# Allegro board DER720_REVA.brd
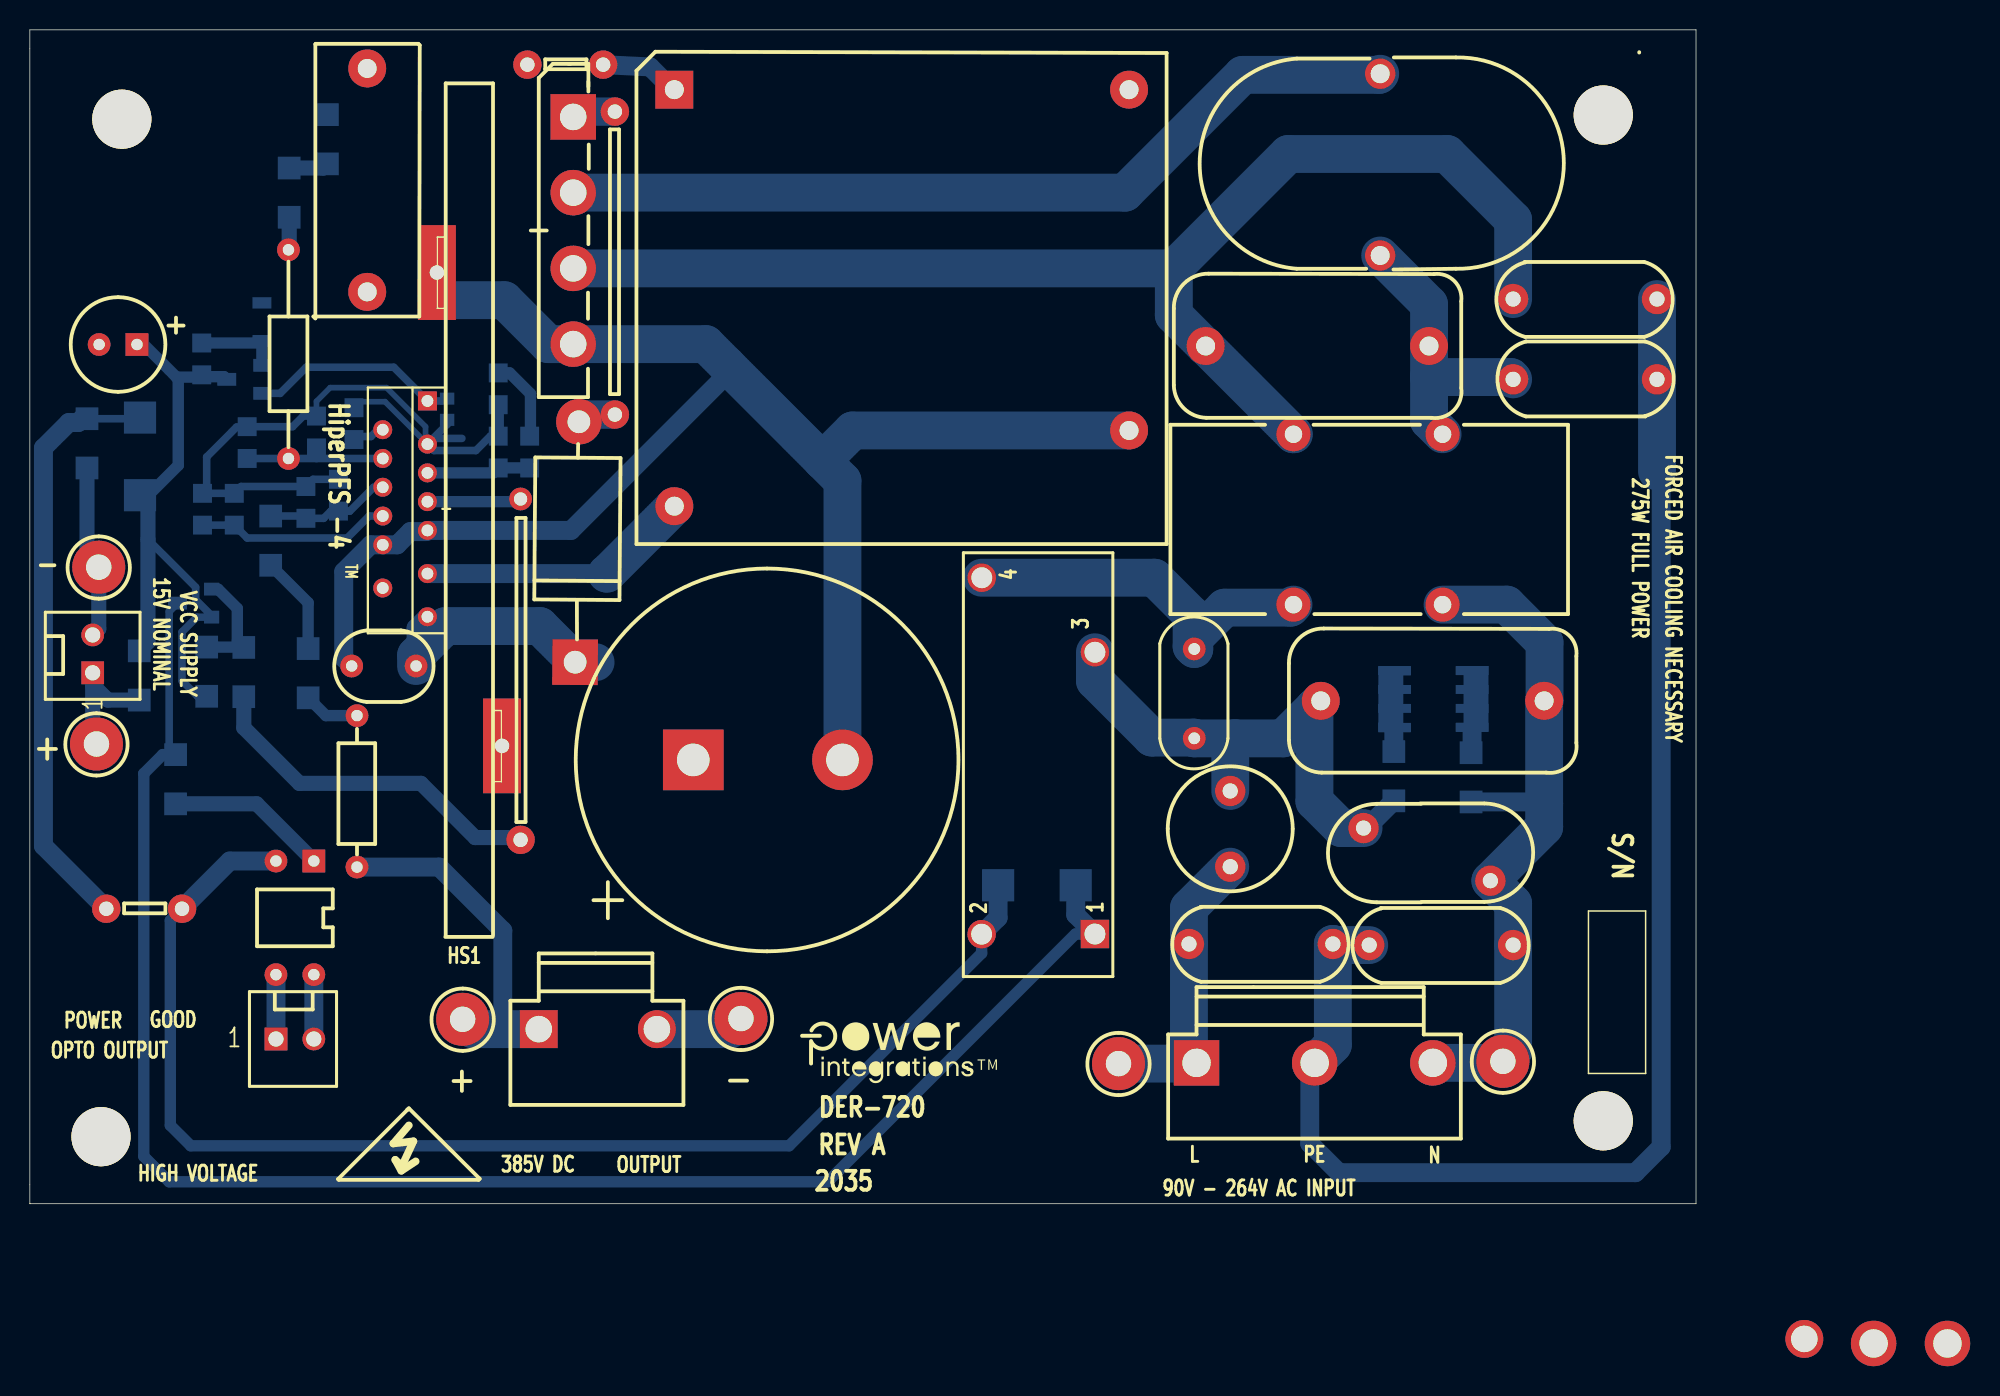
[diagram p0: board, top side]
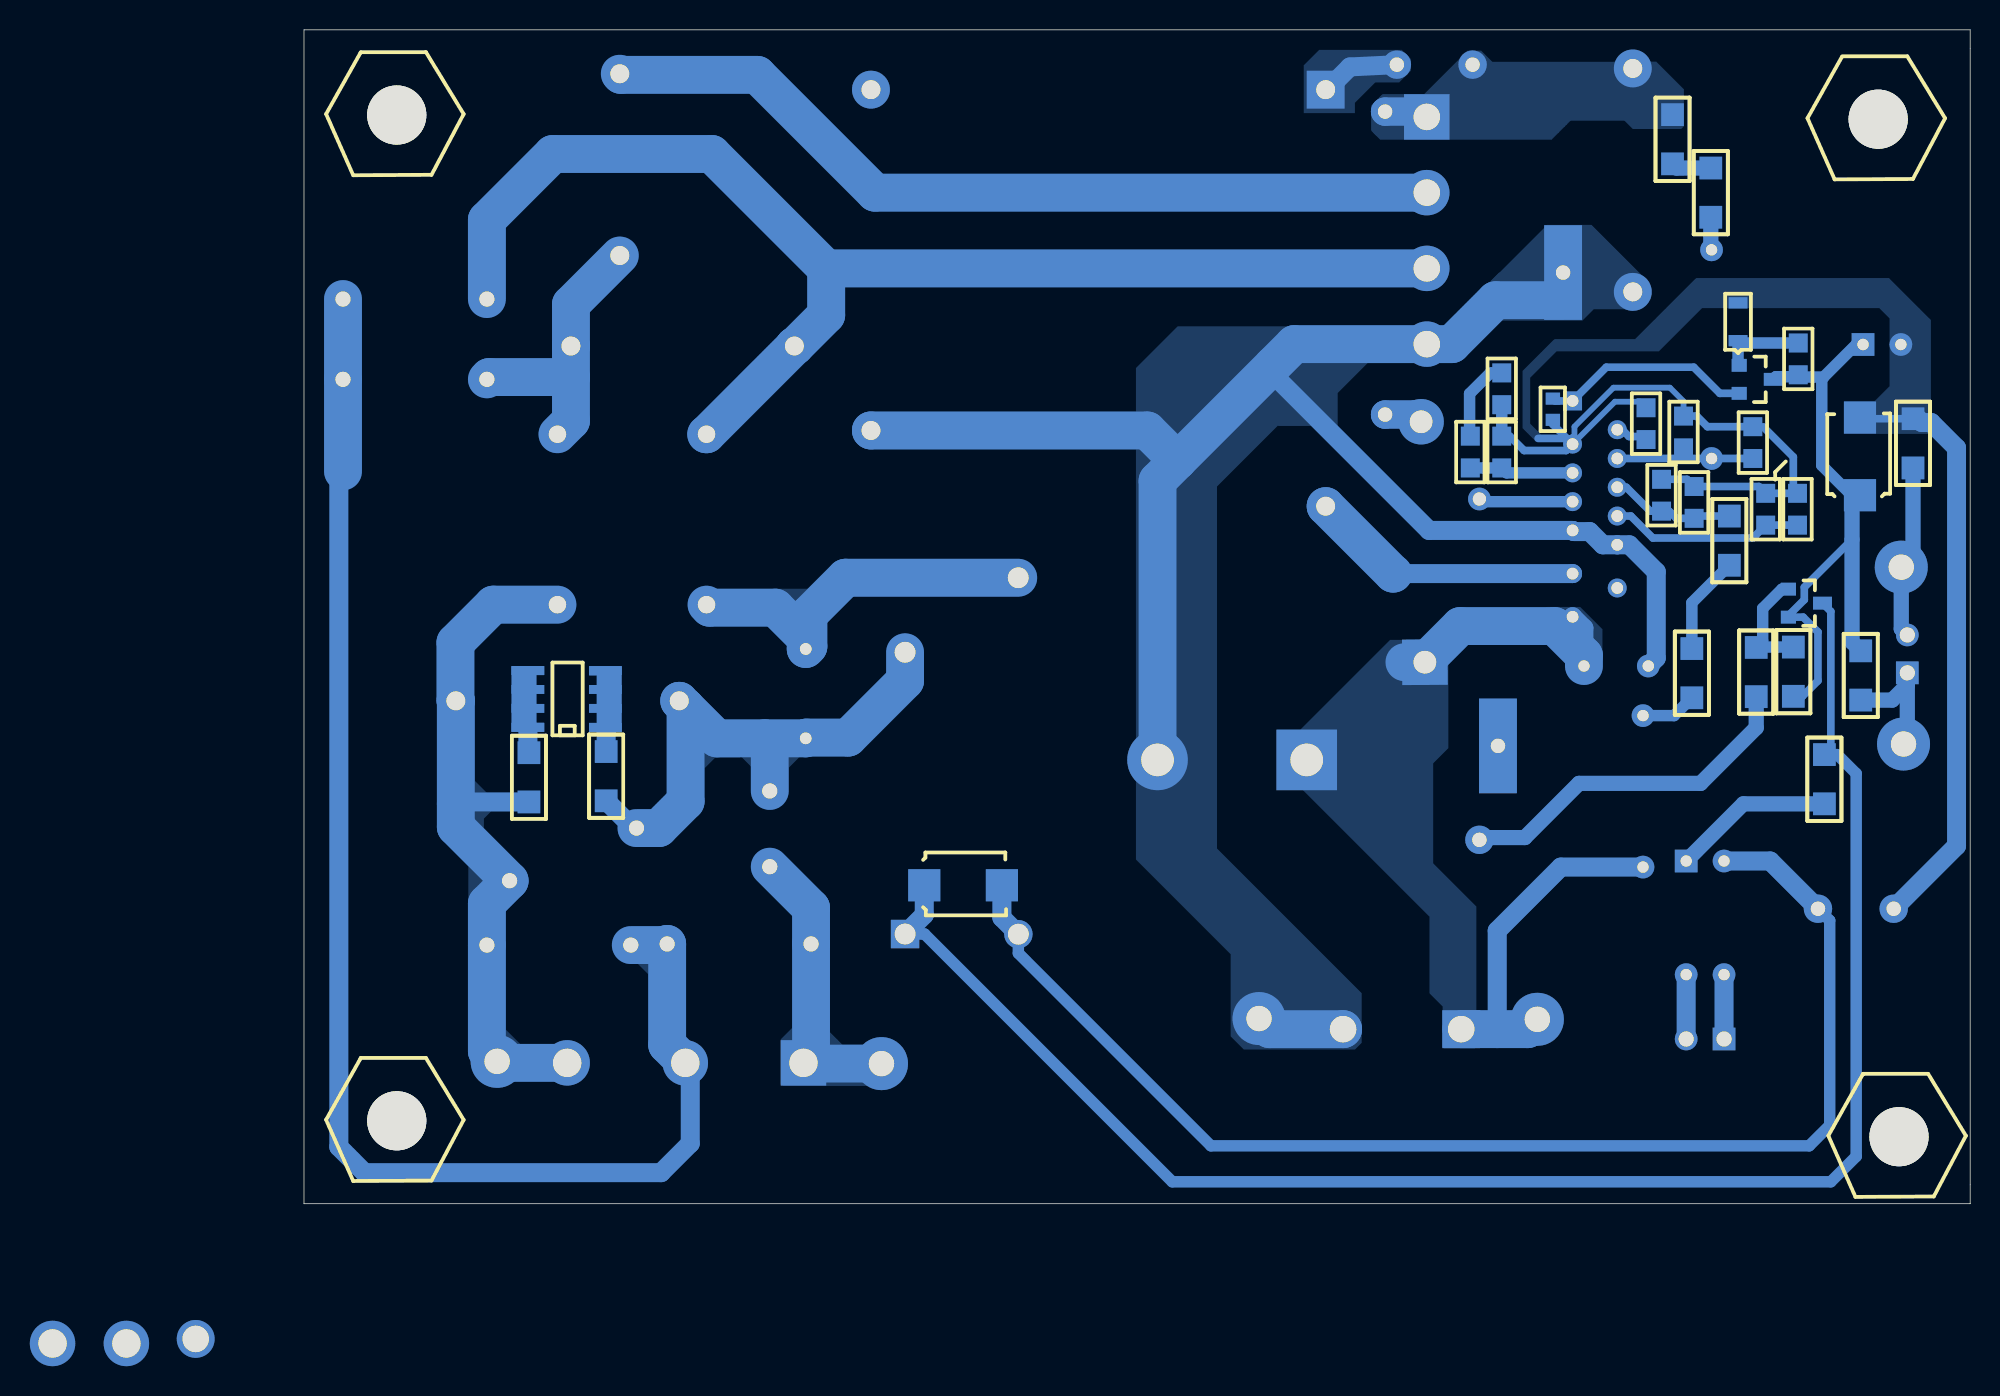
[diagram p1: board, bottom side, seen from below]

Outline 111.76 x 78.74 mm; copper layers: TOP, BOTTOM. Coordinates in mm from the lower left corner of the outline.
Outline path: 0,78.74 111.76,78.74 111.76,0 0,0 0,78.74

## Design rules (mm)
constraint set DEFAULT: min track width 0.508

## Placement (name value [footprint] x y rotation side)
BR1  GBU8K-BP  [PIDAXBRIDGEGBU8]  36.45 72.9 270 top
C1  680 pF  [PINPYCAPRAD470X210LS380040]  77.75 17.42 0 top
C2  680 pF  [PINPYCAPRAD470X210LS380040]  89.84 17.35 0 top
C3  330 nF  [PINPCAPRAD760X380590050]  86.59 33.73 0 top
C4  330 nF  [PINPCAPRAD760X380590050]  78.87 57.53 0 top
C5  680 pF  [PINPYCAPRAD470X210LS380040]  99.49 60.68 0 top
C6  680 pF  [PINPYCAPRAD470X210LS380040]  109.14 55.3 180 top
C7  680 nF  [PI_NP_CAP_RAD717X272LS590D050]  22.63 76.15 270 top
C8  47 uF  [PIPOLCAPCYLD250LS100030]  7.19 57.63 180 top
C9  1 uF  [PISMC0603]  27.99 54 270 bottom
C10  1 uF  [PISMC0805]  21.74 51.26 90 bottom
C11  470 pF  [PISMC0805]  19.23 50.7 90 bottom
C12  100 nF  [PISMC0805]  31.42 49.35 90 bottom
C13  1 uF  [PISMC0805]  31.42 55.73 270 bottom
C14  1 nF  [PISMC0805]  13.72 45.52 90 bottom
C15  10 nF  [PI_NP_CAP250X200LS170D030]  25.91 36.07 180 top
C16  470 pF  [PISMC0805]  20.7 46.46 90 bottom
C17  180 uF  [PIPOLCAPCLYD985LS394086]  44.5 29.79 0 top
D1  S1AB-13-F  [PISMSMB]  70.15 21.36 180 bottom
D2  1N5408-T  [PIDAX800X225060DO15DO201AD]  36.65 34.8 89.6 top
D3  S1AB-13-F  [PISMSMB]  7.39 47.52 90 bottom
F1  5 A  [PI_TR5_SUBMIN_FUSE]  80.52 22.61 90 top
HS1  HEATSINK,  FAB, WITH BRKT,DER394, PI CUST  [PI_HS_DER394_EESIP]  31.06 17.98 90 top
J1  CON5  [PI_HDR_5PIN]  78.26 9.45 270 top
J2  CON2  [PI_MOLEX_2POL]  16.51 11.05 0 top
J3  CON3  [PI_HDR_3PIN_LOCK]  34.14 11.71 270 top
J4  CON2  [PI_MOLEX_2POL]  4.22 35.61 90 top
JP1  J  [PI_JUMPER200]  33.38 76.4 0 top
JP3  J  [PI_JUMPER200]  5.13 19.79 0 top
JP4  J  [PI_JUMPER800]  39.24 73.25 270 top
JP5  J  [PI_JUMPER900]  32.92 24.41 90 top
L1  400 uH  [PI_BOBBIN_BPQ32_20_32-00298-00]  43.23 74.73 0 top
L2  9 mH  [PI_IND_4P_500X1050LS450D46_R1]  84.76 40.18 90 top
L3  330 uH  [PI_TOROID_2P_550X950_LS480_D050]  90.58 63.6 90 top
NOREF  -  []  0 0 90 top
NOREF#2  -  []  -135.54 71.63 0 top
NOREF#3  -  []  0 78.74 0 top
NOREF#4  -  []  51.69 12.65 0 top
NOREF#5  -  []  -213.36 -127.38 0 top
POST-CRKT_BRD_6-32_HEX1  Post Hex, 6-32, snap, 0.375L, NYL  [PIMTGHOLED156]  105.54 5.56 0 top
POST-CRKT_BRD_6-32_HEX2  Post Hex, 6-32, snap, 0.375L, NYL  [PIMTGHOLED156]  6.17 72.75 0 top
POST-CRKT_BRD_6-32_HEX3  Post Hex, 6-32, snap, 0.375L, NYL  [PIMTGHOLED156]  105.54 73.03 0 top
POST-CRKT_BRD_6-32_HEX4  Post Hex, 6-32, snap, 0.375L, NYL  [PIMTGHOLED156]  4.78 4.5 0 top
Q1  MMBT4403  [PISMSOT23132]  12.19 39.34 270 bottom
Q2  MMBT4401LT1G  [PISMSOT23132]  15.49 54.36 270 bottom
R1  510 k  [PISMR1206]  91.49 27.03 90 bottom
R2  510 k  [PISMR1206]  96.67 30.25 270 bottom
R3  10.0 k  [PISMR1206]  11.86 34.04 90 bottom
R4  16.2 k  [PISMR1206]  14.35 37.31 270 bottom
R5  3.01 k  [PISMR1206]  9.78 30.12 270 bottom
R6  1  [PISMR1206]  7.34 33.78 90 bottom
R7  1  [PISMR1206]  3.84 49.35 90 bottom
R8  2.21 k  [PISMR0805]  11.53 55.6 90 bottom
R10  6.2 M  [PISMR1206]  19.96 73.05 270 bottom
R11  6.2 M  [PISMR1206]  17.4 69.47 270 bottom
R12  3.74 M  [PI14WVRESD100LS100D030#2]  17.35 62.69 270 top
R13  162 k  [PISMR0805]  14.58 49.99 90 bottom
R14  30.1 k  [PISMR0805]  33.53 49.35 90 bottom
R15  332 k  [PISMR0805]  11.58 45.52 90 bottom
R16  3.74 M  [PI14WVRESD100LS100D030]  21.95 22.58 90 top
R17  6.2 M  [PISMR1206]  18.67 37.24 270 bottom
R18  6.2 M  [PISMR1206]  16.15 46.13 270 bottom
R19  162 k  [PISMR0805]  18.52 45.97 90 bottom
RL1  SPST NO  [PI_RLY-OMRON-G6RL-1A]  71.45 18.11 90 top
RT1  2.5  [PI_RAD180X395LS235D031]  78.11 31.22 90 top
RV1  320 Vac  [PIDISC500X225LS335X140040]  89.46 25.2 0 top
TP1  CON1  [PITPKEYSTONE125X125]  73.03 9.4 0 top
TP2  CON1  [PITPKEYSTONE125X125]  98.81 9.55 0 top
TP4  CON1  [PITPKEYSTONE125X125]  4.47 30.84 0 top
TP5  CON1  [PITPKEYSTONE125X125]  4.62 42.7 0 top
TP6  CON1  [PITPKEYSTONE125X125]  29.03 12.37 0 top
TP7  CON1  [PITPKEYSTONE125X125]  47.7 12.42 0 top
U1  PFS7727H  [PI_IC_ESIP-16D]  26.67 53.85 270 top
U2  CAP003DG  [PI_IC_SMD_SO8_CAPZERO]  91.54 31.95 90 bottom
U3  LTV817A  [PI_DIP4]  19.05 22.99 180 top
VR1  BZX384-B13,115  [PISMSOD323]  15.57 57.89 90 bottom

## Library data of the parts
BR1 = DISCRETE BRIDGE_+~~-
C1 C2 C5 C6 = CAP NP: tolerance: 20
C3 C4 C9-C16 = CAP NP
C7 = CAP NP: alternate symbols: (pi_np_cap_rad717x272ls590d050_h)
C8 = CAP POL: alternate symbols: (pipolcapcyld250ls100030h); tolerance: 20
C17 = CAP POL
D1 D3 = DIODE
D2 = DIODE: alternate symbols: (pidax800x225060do15do201ad,pidv300x200x060do14wbead)
F1 = FUSE
HS1 = HS-PI_CUSTOM2
J1 = CON5
J2 J4 = CON2
J3 = CON3
JP1 JP3-JP5 = JUMPER_1
L1 = INDUCTOR_DER394_32-00298-00
L2 = INDUCTOR_4P_revB
L3 = INDUCTOR
POST-CRKT_BRD_6-32_HEX1-POST-CRKT_BRD_6-32_HEX4 = POST_CRKT_BRD_6-32_HEX
Q1 = PNP_BEC
Q2 = NPN_BEC
R1-R8 R10 R11 R13-R15 R17-R19 = R
R12 R16 = R: alternate symbols: (pi14wvresd100ls200d030,pi14wresd100ls400d030,pi14wresd100ls500d030)
RL1 = RELAY SPST_NO_OMRON-G6RL
RT1 = THERMISTOR
RV1 = VARISTOR
TP1 TP2 TP4-TP7 = TESTPOINT
U1 = HIPERPFS-4-eSIP-16D_16K: alternate symbols: (piiclbendesiplg_socket)
U2 = CAPZero
U3 = OPTO_DIP
VR1 = DIODE_ZENER

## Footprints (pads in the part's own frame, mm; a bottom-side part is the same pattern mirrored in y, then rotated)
PI14WVRESD100LS100D030
  round 1.524 hole 0.762: 1(0,0) 2(10.16,0)
PI14WVRESD100LS100D030#2
  round 1.524 hole 0.762: 1(-1.295,0) 2(12.7,0)
PI_BOBBIN_BPQ32_20_32-00298-00
  round 2.54 hole 1.27: (30.5,0) 6(0,-27.94) 8(30.5,-22.86)
  rect 2.54x2.54 hole 1.27: 1(0,0)
PI_DIP4
  rect 1.524x1.524 hole 0.762: 1(0,0)
  round 1.524 hole 0.762: 2(2.54,0) 3(2.54,7.62) 4(0,7.62)
PI_HDR_3PIN_LOCK
  rect 2.54x2.54 hole 1.778: 1(0,0)
  round 2.54 hole 1.778: 2(20.777,84.887) 3(0,7.925)
PI_HDR_5PIN
  rect 3.048x3.048 hole 1.905: 1(0,0)
  round 3.048 hole 1.905: 2(18.821,45.415) 3(0,7.925) 4(18.821,50.368) 5(0,15.85)
PI_HS_DER394_EESIP
  rect 6.35x2.54 hole 0.965: 1(12.725,-0.61) 2(44.475,3.759)
PI_IC_ESIP-16D
  rect 1.27x1.27 hole 0.787: 1(0,0)
  round 1.27 hole 0.787: 3(1.93,-2.997) 4(2.896,0) 5(3.861,-2.997) 6(4.826,0) 7(5.791,-2.997) 8(6.756,0) 9(7.722,-2.997) 10(8.687,0) 11(9.652,-2.997) 13(11.582,0) 14(12.548,-2.997) 16(14.478,0)
PI_IC_SMD_SO8_CAPZERO
  rect 0.599x2.2 smd: 1(0,0) 2(1.27,0) 3(2.54,0) 4(3.81,0) 5(3.81,5.199) 6(2.54,5.199) 7(1.27,5.199) 8(0,5.199)
PI_IND_4P_500X1050LS450D46_R1
  round 2.286 hole 1.168: 1(0,-10) 2(11.43,-10) 3(0,0) 4(11.43,0)
PI_JUMPER200
  round 1.905 hole 0.965: 1(0,0) 2(5.08,0)
PI_JUMPER800
  round 1.905 hole 0.965: 1(0,0) 2(20.32,0)
PI_JUMPER900
  round 1.905 hole 0.965: 1(0,0)
  round 1.524 hole 0.889: 2(22.86,0)
PI_MOLEX_2POL
  rect 1.524x1.524 hole 1.016: 1(0,0)
  round 1.524 hole 1.016: 2(2.54,0)
PI_NP_CAP250X200LS170D030
  round 1.524 hole 0.762: 1(0,0) 2(4.318,0)
PI_NP_CAP_RAD717X272LS590D050
  round 2.54 hole 1.27: 1(0,0) 2(14.986,0)
PI_RAD180X395LS235D031
  round 1.524 hole 0.787: 1(0,0) 2(5.994,0)
PI_RLY-OMRON-G6RL-1A
  rect 1.905x1.905 hole 1.397: 1(-0.02,0.008)
  round 1.905 hole 1.397: 2(-0.031,7.607) 3(18.88,0.008) 4(23.878,7.597)
PI_TOROID_2P_550X950_LS480_D050
  round 2.032 hole 1.27: 1(0,0) 2(12.192,0)
PI_TR5_SUBMIN_FUSE
  round 2.032 hole 1.016: 1(0,0) 2(5.08,0)
PIDAX800X225060DO15DO201AD
  rect 3.048x3.048 hole 1.524: 1(1.523,0.087)
  round 3.048 hole 1.524: 2(17.654,-0.048)
PIDAXBRIDGEGBU8
  rect 3.048x3.048 hole 1.778: 1(0,0)
  round 3.048 hole 1.778: 2(5.08,0) 3(10.16,0) 4(15.24,0)
PIDISC500X225LS335X140040
  round 2.032 hole 1.016: 1(0,0) 2(8.509,-3.531)
PIMTGHOLED156
  round 3.962 hole 3.962: 1(0,0)
PINPCAPRAD760X380590050
  round 2.54 hole 1.27: 1(0,0) 2(14.986,0)
PINPYCAPRAD470X210LS380040
  round 2.032 hole 1.016: 1(0,0) 2(9.652,0)
PIPOLCAPCLYD985LS394086
  rect 4.064x4.064 hole 2.184: 1(0,-0.025)
  round 4.064 hole 2.184: 2(10.008,-0.025)
PIPOLCAPCYLD250LS100030
  rect 1.524x1.524 hole 0.762: 1(0,0)
  round 1.524 hole 0.762: 2(2.54,0)
PISMC0603
  rect 0.813x0.965 smd: 1(0,0) 2(1.422,0)
PISMC0805
  rect 1.27x1.27 smd: 1(0,0) 2(2.134,0)
PISMR0805
  rect 1.27x1.27 smd: 1(0,0) 2(2.134,0)
PISMR1206
  rect 1.524x1.524 smd: 1(0,0) 2(3.302,0)
PISMSMB
  rect 2.159x2.159 smd: 1(0,0) 2(5.207,0)
PISMSOD323
  rect 0.762x1.27 smd: 1(0,0) 2(2.54,0)
PISMSOT23132
  rect 0.864x1.016 smd: 1(-1.88,0) 2(0,0)
  rect 0.864x1.27 smd: 3(-0.94,2.286)
PITPKEYSTONE125X125
  round 3.556 hole 1.702: 1(0,0)

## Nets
GND_EARTH: C1.2 C2.1 C5.2 C6.1 J1.3
RTN: BR1.4 C7.2 C15.2 C17.2 HS1.2 J3.3 L1.8 TP7.1 U1.10 U1.11
VRECT: BR1.1 C7.1 JP1.1 JP4.1 R10.1
N07467: C15.1 C17.1 D2.1 J3.1 R16.1 TP6.1 U1.16
N25080: C8.1 D3.1 Q1.2(EMITTER) Q2.3 R3.1 R6.2 R8.1
N182027: C8.2 C9.2 C10.2 C11.2 C12.2 C13.2 C14.2 C16.2 D3.2 JP3.1 R7.2 R13.2 R15.2 R19.2 U1.4 VR1.2
N186578: J4.1 R6.1 TP4.1
N737447: J4.2 R7.1 TP5.1
N1270725: C2.2 C3.2 J1.5 L2.1 R2.2 RV1.2 TP2.1
N1270759: BR1.3(AC2) C4.1 C5.1 L2.4
N1270767: C4.2 C6.2 L2.2 L3.1
N1270943: BR1.2 L3.2
N1271019: R1.2 U2.1 U2.2 U2.3 U2.4
N1271113: C3.1 F1.2 R1.1 RL1.3 RT1.1 RV1.1
N1271129: C1.1 F1.1 J1.1 TP1.1
N1844572: D1.2 JP3.2 RL1.2 U3.2
N1847765: Q1.1 R3.2 R4.1
N1847834: JP5.1 R4.2
N1847930: D1.1 Q1.3 R5.1 RL1.1
N1948021: J2.1 U3.3(E)
N1951038: J2.2 U3.4
N2021552: R2.1 U2.5 U2.6 U2.7 U2.8(NC8)
N2052551: L2.3 RL1.4(NO) RT1.2
N2109009: R16.2 R17.2
N2109013: R17.1 R18.2
N2109017: C16.1 R18.1 R19.1 U1.7
N2109281: JP5.2 U1.8
N2110258: C9.1 Q2.2(EMITTER) U1.1
N2110453: C13.1 R14.2
N2110457: C12.1 R14.1 U1.6
N2110757: C10.1 U1.3
N2114150: R10.2 R11.1
N2114158: R11.2 R12.1
N2114457: C11.1 R12.2 R13.1 U1.5
N2158177: C14.1 R15.1 U1.9
N2163226: JP1.2 L1.1
N2199044: Q2.1 R8.2 VR1.1
N2237206: L1.6 U1.13
N2267541: D2.2 JP4.2
N19475010: R5.2 U3.1

Pads without a net: HS1 1; J1 2 4; J3 2; POST-CRKT_BRD_6-32_HEX1 1; POST-CRKT_BRD_6-32_HEX2 1; POST-CRKT_BRD_6-32_HEX3 1; POST-CRKT_BRD_6-32_HEX4 1; U1 14

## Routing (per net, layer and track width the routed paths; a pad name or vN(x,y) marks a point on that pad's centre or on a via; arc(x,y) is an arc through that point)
GND_EARTH: length 99.1
  BOTTOM w1.27: 109.14,49.12 109.42,49.4 109.42,3.81 107.7,2.08 87.81,2.08 85.85,4.04 85.85,9.12 J1.3
  BOTTOM w2.54: C5.2 C6.1 109.14,49.12 ; C2.1 87.48,17.35 C1.2 87.4,10.67 J1.3
RTN: length 118.5
  BOTTOM w1.27: 27.58,62.48 27.35,60.6 ; C15.2 21.06,36.6 21.06,42.39 22.86,44.2 U1.11 24.64,44.2 25.53,45.09 26.59,45.09 U1.10 36.3,45.16 46.75,55.61 46.75,56.25
  BOTTOM w2.54: 53.16,49.84 55.19,51.87 L1.8 ; 53.16,49.84 54.51,48.49 C17.2 ; 53.16,49.84 45.34,57.66 BR1.4 34.77,57.66 31.83,60.6 27.35,60.6 ; J3.3 46.99,11.71 TP7.1
VRECT: length 3.2
  BOTTOM w0.762: 36.7,72.9 BR1.1
  BOTTOM w1.905: BR1.1 36.8,73.25 JP4.1
N07467: length 41.2
  BOTTOM w0.762: 21.84,22.73 R16.1
  BOTTOM w1.27: 25.91,36.78 25.91,38.61 U1.16 ; R16.1 27.46,22.58 31.72,18.31 31.72,11.71
  BOTTOM w2.54: 37.95,36.32 D2.1 36.58,36.37 34.2,38.75 27.88,38.75 25.91,36.78 C15.1 ; J3.1 29.69,11.71 TP6.1
N25080: length 42.1
  BOTTOM w0.508: R3.1 11.25,34.04 10.21,35.08 10.21,38.35 11.2,39.34 Q1.2 12.19,39.45 11.13,40.51 11.13,41.35 7.92,44.55
  BOTTOM w0.762: C8.1 7.65,57.63 9.83,55.45 ; D3.1 7.95,47.52 9.96,49.53 9.96,55.32 9.83,55.45 ; Q2.3 13.03,55.47 11.66,55.47 R8.1 11.38,55.45 9.83,55.45
  BOTTOM w1.016: R6.2 7.92,37.67 7.92,46.99 D3.1
N182027: length 89.9
  BOTTOM w0.254: U1.4 26.54,51.08
  BOTTOM w0.381: C11.2 19.23,53.82 20.14,54.74 23.93,54.74 26.54,52.12 26.54,51.08 23.83,53.8 22.12,53.8 21.74,53.42 C10.2 ; U1.4 26.67,51.33 ; 26.67,51.33 26.67,51.44 26.57,51.44 26.67,51.33
  BOTTOM w0.508: C16.2 19,48.59 R19.2 14.17,48.11 C14.2 R15.2 11.86,48.13 11.86,50.09 13.87,52.1 14.55,52.1 R13.2 17.63,52.12 18.34,52.83 C11.2 ; R7.2 7.32,52.65 D3.2 ; C12.2 30.89,51.49 29.92,50.52 27.1,50.52 U1.4 27.05,51.33 ; 27.05,51.33 27.99,52.27 C9.2 ; 27.05,51.33 28.98,51.33
  BOTTOM w0.762: C13.2 C12.2
  BOTTOM w1.27: JP3.1 0.91,24 0.91,50.7 2.62,52.4 3.25,52.4 3.51,52.65 R7.2
N186578: length 8.4
  BOTTOM w1.016: 4.22,34.8 4.22,31.09 TP4.1 ; 4.22,34.8 5.23,33.78 R6.1 ; 4.22,34.8 J4.1
N737447: length 11.7
  BOTTOM w1.016: J4.2 4.62,38.56 TP5.1 3.84,43.48 R7.1
N1270725: length 48.1
  BOTTOM w1.27: 101.57,26.82 101.45,26.95 R2.2
  BOTTOM w2.54: L2.1 99.06,40.18 101.6,37.64 101.6,33.76 C3.2 101.57,25.27 RV1.2 99.49,20.14 C2.2 99.49,10.24 TP2.1 98.7,9.45 J1.5
N1270759: length 87.9
  BOTTOM w2.54: 84.79,51.61 L2.4 78.87,57.51 C4.1 78.82,57.53 76.73,59.61 76.73,62.74 ; 76.73,62.74 BR1.3 ; 76.73,62.74 84.4,70.41 95.07,70.41 99.49,65.99 C5.1
N1270767: length 19.4
  BOTTOM w2.54: L2.2 93.85,52.52 93.85,55.45 ; 93.85,55.45 93.85,60.33 L3.1 ; 93.85,55.45 99.34,55.45 C6.2
N1270943: length 57.4
  BOTTOM w2.54: L3.2 90.5,75.72 81.36,75.72 73.46,67.82 BR1.2
N1271019: length 1.6
  BOTTOM w1.27: U2.1 91.49,31.9 R1.2
N1271113: length 36.5
  BOTTOM w1.27: R1.1 89.66,25.2 RV1.1
  BOTTOM w2.54: 86.16,33.31 C3.1 ; 86.16,33.31 84.07,31.22 80.85,31.22 ; 86.16,33.31 86.16,26.99 87.96,25.2 RV1.1 ; 80.85,31.22 RT1.1 78.05,31.27 75.26,31.27 71.44,35.08 RL1.3 ; 80.85,31.22 80.52,30.89 F1.2
N1271129: length 19.8
  BOTTOM w2.54: TP1.1 78.21,9.4 J1.1 77.75,9.96 C1.1 77.75,19.84 F1.1
N1844572: length 87.8
  BOTTOM w0.762: RL1.2 63.84,16.8 50.93,3.89 10.79,3.89 9.42,5.26 9.42,19 JP3.2
  BOTTOM w1.27: U3.2 13.41,22.99 JP3.2 ; D1.2 64.95,19.18 RL1.2
N1847765: length 7.5
  BOTTOM w0.762: 14.33,37.34 R4.1 ; 14.33,37.34 13.92,37.74 13.92,39.93 12.62,41.22 Q1.1 ; 14.33,37.34 R3.2
N1847834: length 23.8
  BOTTOM w1.016: R4.2 14.35,31.93 18.08,28.19 26.24,28.19 29.87,24.56 32.77,24.56 JP5.1
N1847930: length 114.1
  BOTTOM w0.508: R5.1 9.35,30.56 9.35,39.73 Q1.3
  BOTTOM w0.762: RL1.1 70.13,18.09 53.52,1.47 9.35,1.47 7.65,3.17 7.65,28.85 8.92,30.12 R5.1
  BOTTOM w1.27: D1.1 70.15,19.38 RL1.1
N1948021: length 4.3
  BOTTOM w1.27: 16.51,15.37 J2.1
N1951038: length 4.3
  BOTTOM w1.27: 19.05,15.37 J2.2
N2021552: length 1.7
  BOTTOM w1.27: U2.8 96.74,30.32 R2.1
N2052551: length 25.8
  BOTTOM w2.54: L2.3 84.56,39.98 80.14,39.98 78.11,37.95 RT1.2 77.93,37.39 77.93,39.5 75.44,41.99 RL1.4
N2109009: length 3.9
  BOTTOM w0.762: R17.2 19.86,32.74 R16.2
  BOTTOM w1.27: 21.84,32.77 R16.2
N2109013: length 6.6
  BOTTOM w0.762: R17.1 18.67,40.31 R18.2
N2109017: length 8.4
  BOTTOM w0.508: U1.7 23.06,48.06 21.46,46.46 C16.1 20.19,46.46 19.71,45.97 R19.1 18.36,46.13 R18.1
N2109281: length 6.3
  BOTTOM w0.762: U1.8 32.74,47.09 JP5.2
N2110258: length 14.2
  BOTTOM w0.508: Q2.2 16.79,54.36 18.54,56.11 24.41,56.11 U1.1 27.84,53.85 C9.1
N2110453: length 5.6
  BOTTOM w0.762: R14.2 33.58,51.54 33.58,54.33 32.18,55.73 C13.1
N2110457: length 7
  BOTTOM w0.762: U1.6 31.09,49.02 C12.1 R14.1
N2110757: length 2.2
  BOTTOM w0.508: C10.1 21.95,51.46 22.89,51.46 23.34,51.92 U1.3
N2114150: length 2.7
  BOTTOM w1.016: R10.2 19.68,69.47 R11.1
N2114158: length 2.2
  BOTTOM w1.016: 17.4,66.17 17.4,64.03 R12.1
N2114457: length 9.8
  BOTTOM w0.508: R12.2 R13.1 ; R12.2 19.23,49.99 ; R12.2 17.37,50.01 ; 19.23,49.99 U1.5 ; 19.23,49.99 C11.1
N2158177: length 13.1
  BOTTOM w0.508: U1.9 22.76,46.13 21.29,44.65 14.58,44.65 C14.1 R15.1
N2163226: length 5.4
  BOTTOM w1.27: JP1.2 41.61,76.25 43.18,74.68
N2199044: length 5.8
  BOTTOM w0.762: R8.2 15.42,57.73 VR1.1 15.57,56.31 Q2.1
N2237206: length 18.4
  BOTTOM w1.27: U1.13 38.68,42.27
  BOTTOM w2.54: L1.6 38.71,42.27 38.68,42.27
N2267541: length 2.6
  BOTTOM w1.905: D2.2 37.31,52.93 JP4.2
N19475010: length 10.9
  BOTTOM w1.016: R5.2 15.21,26.82 U3.1

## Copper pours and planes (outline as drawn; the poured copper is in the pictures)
GND_EARTH on BOTTOM: 89.79,16.31 89.59,16.31 88.04,14.76 87.35,15.44 87.35,16.69 89.41,16.69
RTN on BOTTOM: 42.42,52.17 46.41,52.17 46.43,52.2 50.52,48.11 50.52,23.83 40.82,14.12 40.82,10.79 41.27,10.34 48.72,10.34 49.61,11.23 49.61,16.74 55.96,23.09 55.96,56.06 53.16,58.85 41.61,58.85 39.85,57.1 39.85,56.95 42.42,54.38
RTN on BOTTOM: 28.37,65.66 31.55,62.48 31.57,62.48 33.02,61.04 33.05,61.04 33.05,59.23 26.01,59.23 25.25,59.99 22.15,59.99 21.59,60.55 21.59,61.85 25.4,65.66
VRECT on BOTTOM: 37.9,74.42 39.42,74.42 40.18,73.66 40.18,71.98 39.83,71.63 37.9,73.56
VRECT on BOTTOM: 37.97,74.42 36.63,74.42 33.71,77.34 32.8,77.34 32.05,76.59 23.93,76.59 23.91,76.61 21.06,76.61 19.2,74.75 19.2,72.26 19.38,72.09 22.63,72.09 23.19,72.64 26.8,72.64 28.07,71.37 39.57,71.37 40.03,71.83 40.03,72.36
N07467 on BOTTOM: 28.57,40.03 24.79,36.25 24.66,36.25 24.66,38.53 26.16,40.03
N07467 on BOTTOM: 35,37.82 35,30.56 36.02,29.54 36.02,22.83 33.12,19.94 33.12,10.52 33.22,10.41 35.31,10.41 35.38,10.49 35.38,11.13 35.38,13.23 36.27,14.12 36.27,19.25 45.06,28.04 45.06,31.67 38.91,37.82
N182027 on BOTTOM: 28.7,51.16 28.68,51.18 28.68,51.49 29.51,52.32 29.51,55.4 27.74,57.18 20.88,57.18 17.98,60.07 10.44,60.07 10.43,60.06 10.43,60.07 6.1,60.07 5.41,59.39 5.41,54.84 6.4,53.85 8.46,53.85 8.46,51.64 2.77,51.64 2.64,51.77 2.64,59.28 5.45,62.09 18.38,62.09 22.48,57.99 27.89,57.99 30.02,55.85 30.02,52.02 29.16,51.16
N1270725 on BOTTOM: 100.51,28.57 99.03,27.1 99.03,26.49 99.69,25.83 99.69,24.64 99.57,24.51 101.47,24.51 102.01,25.04 102.01,28.14 101.57,28.57
N1270725 on BOTTOM: 96.82,10.34 96.88,10.34 98.7,12.17 98.83,12.04 98.83,9.78 97,9.78 96.82,9.96
N1270725 on BOTTOM: 100.74,20.22 100.74,23.06 99.36,23.06 99.36,20.22
N1271019 on BOTTOM (solid shape): 92.63,35.43 92.13,35.43 92.13,32.23 92.63,32.23 92.63,31.62 90.45,31.62 90.45,36.04 92.63,36.04
N1271113 on BOTTOM: 78.38,30.1 79.63,28.85 81.31,28.85 82.46,30.01 82.55,29.92 84.18,29.92 85.39,28.7 85.78,29.08 85.78,30.73 85.67,30.84 78.74,30.84 78.38,30.48
N1271129 on BOTTOM: 75.01,9.83 75.01,10.03 77.29,12.32 78.49,12.32 79.78,11.02 79.78,8.05 79.63,7.9 73.1,7.9 72.44,8.56 72.44,9.91 74.93,9.91
N2021552 on BOTTOM (solid shape): 97.84,31.65 95.66,31.65 95.66,32.26 96.16,32.26 96.16,35.46 95.66,35.46 95.66,36.07 97.84,36.07
N2052551 on BOTTOM: 80.19,41.25 80.19,39.83 77.42,39.83 77.42,41.25
N2163226 on BOTTOM: 43.66,77.39 38.13,77.39 37.52,76.78 37.52,76 38.3,75.21 39.9,75.21 41.27,73.84 41.27,73.15 44.7,73.15 44.7,76.35

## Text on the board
Ref Des/Assembly Bottom: -
Ref Des/Silkscreen Top: TM | OPTO OUTPUT | POWER | HIGH VOLTAGE | GOOD | 385V DC | OUTPUT | 90V - 264V AC INPUT | L | PE | N | 15V NOMINAL | VCC SUPPLY | 275W FULL POWER | FORCED AIR COOLING NECESSARY | 2035 | REV A | DER-720 | HiperPFS -4 | S/N
DIMENSION: 13   MATERIALFR4 COPPER 2oz THICKNESS 0.062" | SLOT OUTLINE | DELETE THESE PINS.
NCLEGEND-1-2: FIGURE | FINISHED_SIZE | 30.0 | 31.0 | 35.0 | 38.0 | 40.0 | 46.0 | 50.0 | 55.0 | 60.0 | 67.0 | 70.0 | 75.0 | 86.0 | 156.0 | DRILL CHART: TOP to BOTTOM | ALL UNITS ARE IN MILS | PLATED | QTY | 12 | 15 | 1 | 9 | 16 | 4 | 2 | 6 | 7 | 5
